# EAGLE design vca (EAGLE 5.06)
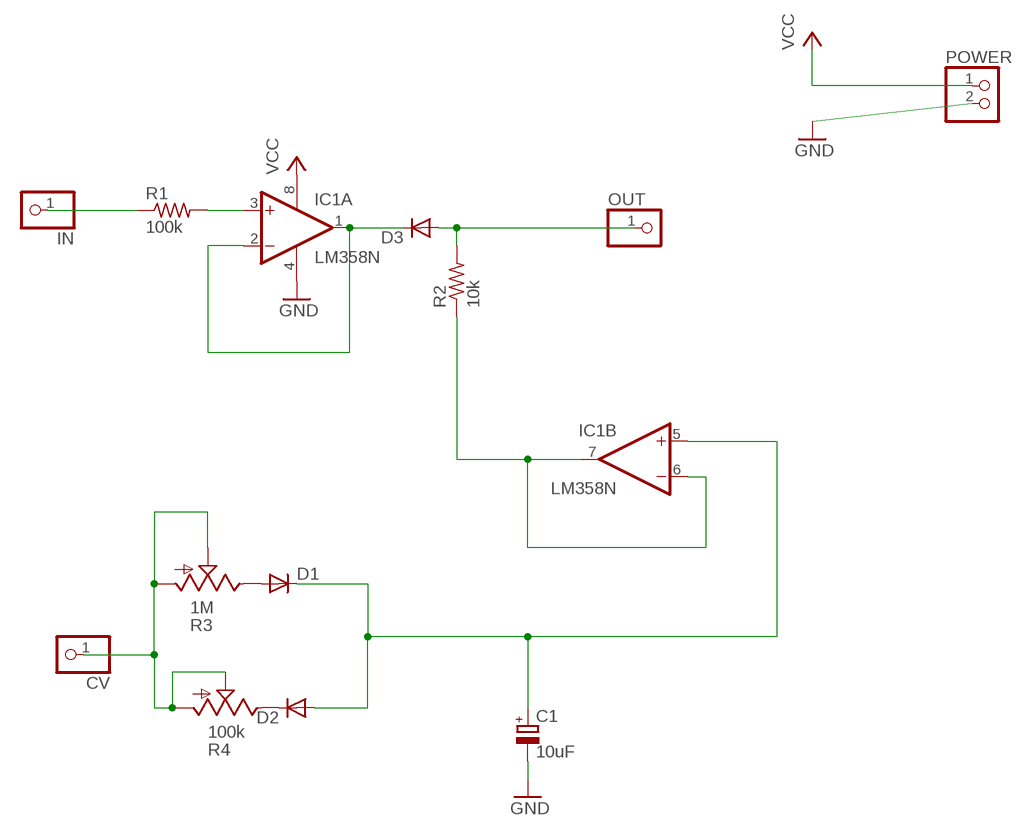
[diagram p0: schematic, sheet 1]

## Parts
C1  10uF  CPOL-EUE5-10.5  [E5-10,5]
CV  PINHD-1X1  [1X01]
D1  DIODE-DO07  [DO07]
D2  DIODE-DO07  [DO07]
D3  DIODE-DO07  [DO07]
IC1  LM358N  [DIL08]
IN  PINHD-1X1  [1X01]
OUT  PINHD-1X1  [1X01]
POWER  PINHD-1X2  [1X02]
R1  100k  R-US_0207/10  [0207/10]
R2  10k  R-US_0207/10  [0207/10]
R3  1M  TRIM_US-RJ9W  [RJ9W]
R4  100k  TRIM_US-RJ9W  [RJ9W]

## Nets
GND: C1.- IC1.4(P:V-) POWER.2
N$1: IN.1 R1.1
N$2: IC1.3(A:+IN) R1.2
N$3: D3.C IC1.1(A:OUT) IC1.2(A:-IN)
N$4: D3.A OUT.1 R2.2
N$5: IC1.6(B:-IN) IC1.7(B:OUT) R2.1
N$6: D2.C R4.E
N$7: C1.+ D1.C D2.A IC1.5(B:+IN)
N$9: D1.A R3.E
N$10: CV.1 R3.A R3.S R4.A R4.S
VCC: IC1.8(P:V+) POWER.1

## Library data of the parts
C1 = resistor:CPOL-EU: POLARIZED CAPACITOR, European symbol
CV IN OUT = pinhead:PINHD-1X1: PIN HEADER
D1-D3 = diode:DIODE-: DIODE
IC1 = linear:LM358: OP AMP also LM158; LM258; LM2904 Source: http://cache.national.com/ds/LM/LM158.pdf
POWER = pinhead:PINHD-1X2: PIN HEADER
R1 R2 = resistor:R-US_: RESISTOR, American symbol
R3 R4 = pot:TRIM_US-: POTENTIOMETER

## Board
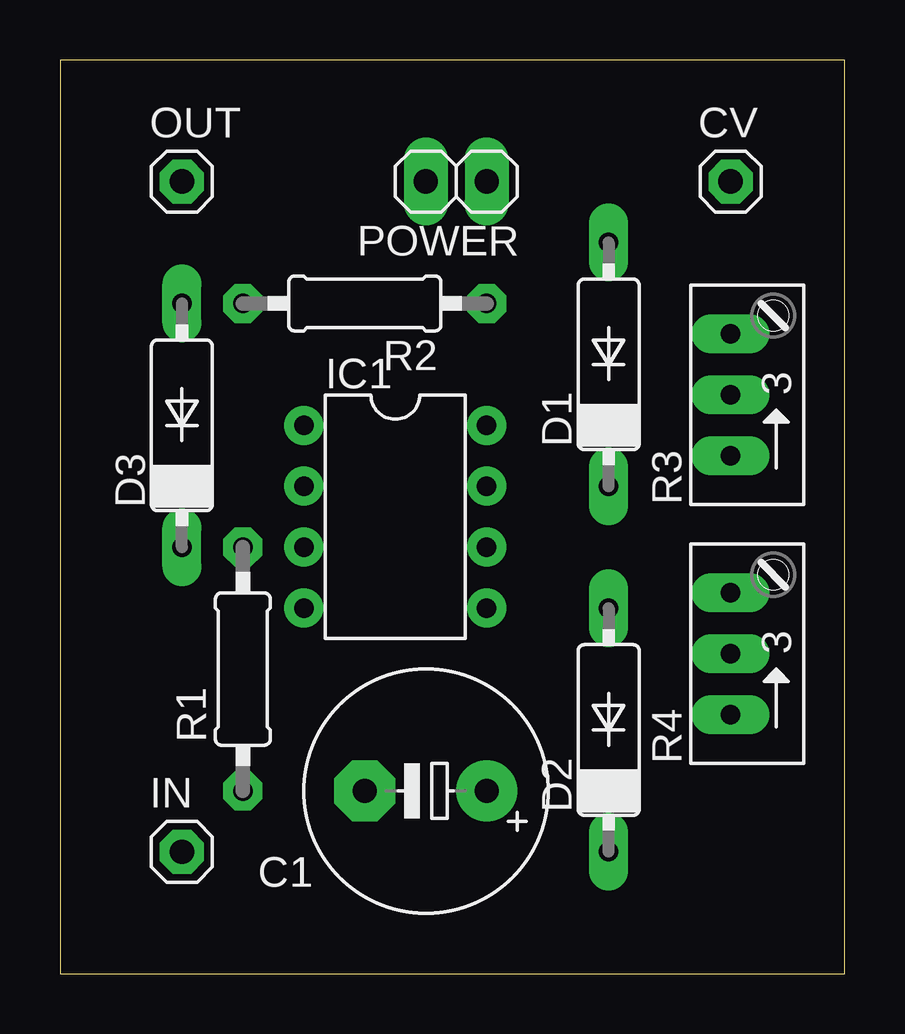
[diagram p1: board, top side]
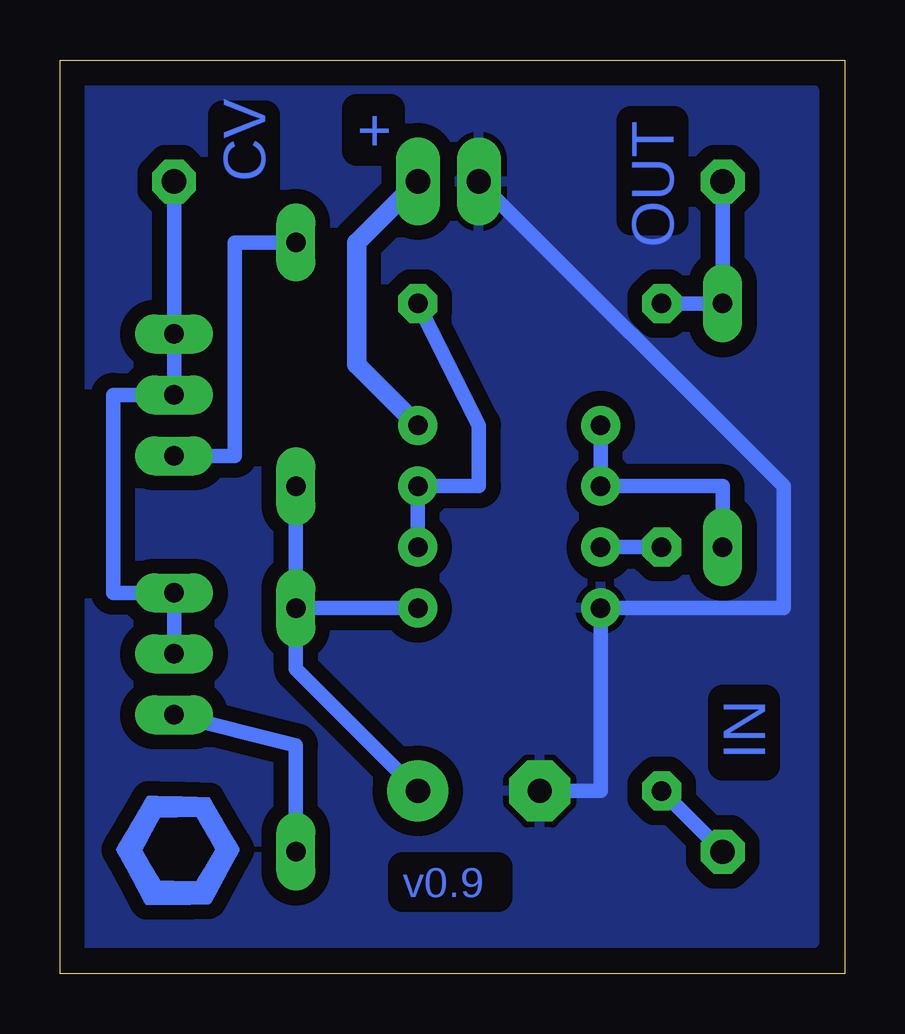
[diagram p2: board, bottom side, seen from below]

Size 32.69 x 38.09 mm. Coordinates in mm from the lower left corner, seen from the top.
Outline: 0,0 32.69,0 32.69,38.09 0,38.09 0,0
Copper layers (1*16): Top 0.035mm / dielectric 1.5mm / Bottom 0.035mm
Design rules "default_24mil": minimum track width 24mil, minimum drill 24mil, track to track 24mil, track to pad 24mil, pad to pad 24mil, via to via 24mil, smd to smd 8mil, copper to edge 40mil, drill to drill 8mil, minimum pad ring 16mil, minimum via ring 12mil, stop-mask expansion 4mil, vias tented up to drill 0mil, thermal gap 10mil

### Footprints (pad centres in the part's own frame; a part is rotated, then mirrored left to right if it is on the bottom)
E5-10,5 = drill 1.016 pad 2.54 round: + -2.54,0 | drill 1.016 pad 2.54 octagon: - 2.54,0
1X01 = drill 1.016 octagon: 1 0,0
DO07 = drill 0.813 long: A 5.08,0; C -5.08,0
DIL08 = drill 0.813 pad 1.27 round: 1 -3.81,-3.81; 2 -1.27,-3.81; 3 1.27,-3.81; 4 3.81,-3.81; 5 3.81,3.81; 6 1.27,3.81; 7 -1.27,3.81; 8 -3.81,3.81
1X02 = drill 1.016 long: 1 -1.27,0; 2 1.27,0
0207/10 = drill 0.813 octagon: 1 -5.08,0; 2 5.08,0
RJ9W = drill 0.813 long: A 2.54,0.635; E -2.54,0.635; S 0,0.635

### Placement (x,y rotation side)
C1  15.24,7.62 180 top
CV  27.94,33.02 0 top
D1  22.86,25.4 90 top
D2  22.86,10.16 90 top
D3  5.08,22.86 90 top
IC1  13.97,19.05 270 top
IN  5.08,5.08 0 top
OUT  5.08,33.02 0 top
POWER  16.51,33.02 180 top
R1  7.62,12.7 90 top
R2  12.7,27.94 180 top
R3  28.58,24.13 90 top
R4  28.58,13.34 90 top

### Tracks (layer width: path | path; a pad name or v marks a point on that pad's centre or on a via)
GND
  Bottom 0.61: C1.- 10.16,7.62 IC1.4 2.54,15.24 2.54,20.32 POWER.2
  pour Bottom: 1.27,36.83 1.27,1.27 31.75,1.27 31.75,36.83
N$1
  Bottom 0.61: IN.1 R1.1
N$2
  Bottom 0.61: R1.2 IC1.3
N$3
  Bottom 0.61: D3.C 5.08,20.32 IC1.2 IC1.1
N$4
  Bottom 0.61: R2.2 D3.A OUT.1
N$5
  Bottom 0.61: IC1.6 IC1.7 15.24,20.32 15.24,22.86 R2.1
N$6
  Bottom 0.61: R4.E 22.86,9.52 D2.C
N$7
  Bottom 0.61: D2.A D1.C | D2.A IC1.5 | D2.A 22.86,12.7 C1.+
N$9
  Bottom 0.61: D1.A 25.4,30.48 25.4,21.59 R3.E
N$10
  Bottom 0.61: R4.S R4.A 30.48,15.88 30.48,24.13 R3.S R3.A CV.1
VCC
  Bottom 0.813: POWER.1 20.32,30.48 20.32,25.4 IC1.8
(copper drawn outside any net)
  shapes: Bottom area x570

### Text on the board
Bottom: OUT | + | CV | IN | v0.9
